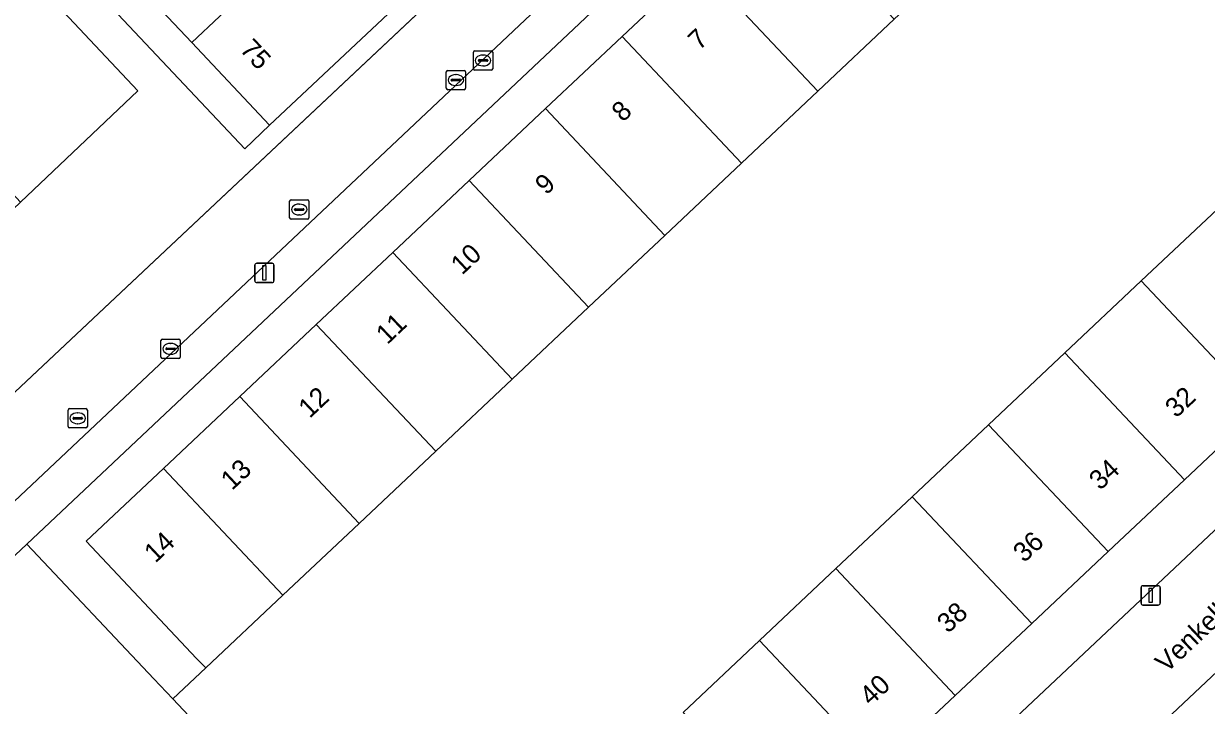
# Model space of a CAD drawing. Extents: x 162542 to 163147, y 380779 to 381521.
# Drawn here: x 162806.1 to 162867.2, y 381217.9 to 381253.1 of the extents above; entities that cross this region are included whole.
import ezdxf

# ---------------------------------------------------------------- set-up
doc = ezdxf.new("R2010")
doc.units = 0
for name, color, linetype in [('IMGEO_Erf', 7, 'Continuous'), ('IMGEO_Groenvoorziening', 7, 'Continuous'), ('IMGEO_Hek', 7, 'Continuous'), ('IMGEO_Kolk', 7, 'Continuous'), ('IMGEO_Lichtmast', 7, 'Continuous'), ('IMGEO_Openbare_ruimte_label', 7, 'Continuous'), ('IMGEO_Pand', 7, 'Continuous'), ('IMGEO_Pand_nummerreeks', 7, 'Continuous'), ('IMGEO_Rioolput', 7, 'Continuous'), ('IMGEO_Voetpad_open', 7, 'Continuous')]:
    doc.layers.add(name, color=color, linetype=linetype)

msp = doc.modelspace()

# ---------------------------------------------------------------- linework, layer by layer
at = {"layer": 'IMGEO_Erf'}
msp.add_lwpolyline([(162792.465, 381275.869), (162788.714, 381279.854), (162784.843, 381283.967), (162781.103, 381287.941), (162777.68, 381291.577), (162773.745, 381295.758), (162770.206, 381299.518), (162766.679, 381303.265), (162762.829, 381307.356), (162758.929, 381311.5), (162757.59, 381310.24), (162817.504, 381246.682), (162818.793, 381247.896), (162814.765, 381252.175), (162810.736, 381256.457), (162807.365, 381260.038), (162803.495, 381264.149), (162799.627, 381268.26), (162795.923, 381272.195)], close=True, dxfattribs=at)
for points in [[(162871.275, 381275.979), (162865.48, 381282.064), (162806.242, 381226.227), (162812.798, 381219.271), (162813.785, 381218.224), (162815.491, 381219.831), (162815.018, 381220.322), (162809.309, 381226.383), (162813.298, 381230.14), (162817.251, 381233.863), (162821.203, 381237.586), (162825.156, 381241.309), (162829.109, 381245.032), (162833.061, 381248.755), (162837.014, 381252.478), (162840.967, 381256.202), (162844.919, 381259.924), (162848.872, 381263.648), (162852.825, 381267.37), (162856.777, 381271.093), (162860.73, 381274.817), (162864.682, 381278.539), (162869.056, 381273.89)], [(162837.429, 381198.492), (162894.031, 381251.782)], [(162870.04, 381233.279), (162866.091, 381229.56), (162862.142, 381225.842), (162858.193, 381222.124), (162854.244, 381218.405), (162850.296, 381214.687)]]:
    msp.add_lwpolyline(points, dxfattribs=at)
at = {"layer": 'IMGEO_Groenvoorziening'}
msp.add_lwpolyline([(162789.418, 381273.655), (162788.933, 381269.872), (162795.678, 381260.305), (162801.834, 381251.14), (162800.589, 381249.668), (162805.915, 381243.918), (162811.977, 381249.676)], close=True, dxfattribs=at)
at = {"layer": 'IMGEO_Hek'}
msp.add_lwpolyline([(162758.166, 381200.425), (162772.303, 381209.99), (162785.212, 381218.724), (162787.433, 381220.358), (162797.686, 381227.138), (162801.587, 381230.307), (162862.582, 381287.674)], dxfattribs=at)
at = {"layer": 'IMGEO_Kolk'}
for p, q in [((162827.922, 381249.806), (162827.922, 381250.658)), ((162827.997, 381250.732), (162828.849, 381250.732)), ((162828.181, 381250.226), (162828.181, 381250.238)), ((162828.224, 381250.275), (162828.622, 381250.275)), ((162828.41, 381250.512), (162828.435, 381250.512)), ((162828.665, 381250.238), (162828.665, 381250.226)), ((162828.923, 381250.658), (162828.923, 381249.806)), ((162828.849, 381249.732), (162827.997, 381249.732)), ((162828.619, 381250.189), (162828.221, 381250.189)), ((162828.433, 381249.952), (162828.408, 381249.952)), ((162813.245, 381236.831), (162814.097, 381236.831)), ((162813.17, 381235.905), (162813.17, 381236.757)), ((162813.429, 381236.325), (162813.429, 381236.337)), ((162813.867, 381236.288), (162813.469, 381236.288)), ((162813.472, 381236.374), (162813.87, 381236.374)), ((162813.658, 381236.611), (162813.683, 381236.611)), ((162813.913, 381236.337), (162813.913, 381236.325)), ((162814.171, 381236.757), (162814.171, 381235.905)), ((162814.097, 381235.831), (162813.245, 381235.831)), ((162813.681, 381236.051), (162813.656, 381236.051))]:
    msp.add_line(p, q, dxfattribs=at)
for points in [[(162827.922, 381249.806), (162827.922, 381250.658)], [(162827.997, 381250.732), (162828.849, 381250.732)], [(162828.923, 381250.658), (162828.923, 381249.806)], [(162828.849, 381249.732), (162827.997, 381249.732)], [(162813.245, 381236.831), (162814.097, 381236.831)], [(162813.17, 381235.905), (162813.17, 381236.757)], [(162814.171, 381236.757), (162814.171, 381235.905)], [(162814.097, 381235.831), (162813.245, 381235.831)]]:
    msp.add_lwpolyline(points, dxfattribs=at)
for centre, radius, start, end in [((162827.999, 381250.656), 0.0765, 91.55205, 178.44795), ((162827.999, 381250.656), 0.0765, 91.55205, 178.44795), ((162828.221, 381250.235), 0.0403, 85.87752, 175.75265), ((162828.626, 381250.237), 0.0386, 1.73085, 96.63898), ((162828.847, 381250.656), 0.0765, 1.55205, 88.44795), ((162828.847, 381250.656), 0.0765, 1.55205, 88.44795), ((162827.999, 381249.808), 0.0765, 181.55205, 268.44795), ((162827.999, 381249.808), 0.0765, 181.55205, 268.44795), ((162828.218, 381250.225), 0.0366, 178.93798, 274.71019), ((162828.622, 381250.232), 0.043, 264.86636, 352.45326), ((162828.847, 381249.808), 0.0765, 271.55205, 358.44795), ((162828.847, 381249.808), 0.0765, 271.55205, 358.44795), ((162813.247, 381236.755), 0.0765, 91.55205, 178.44795), ((162813.247, 381236.755), 0.0765, 91.55205, 178.44795), ((162814.095, 381236.755), 0.0765, 1.55205, 88.44795), ((162814.095, 381236.755), 0.0765, 1.55205, 88.44795), ((162813.469, 381236.334), 0.0403, 85.87752, 175.75265), ((162813.466, 381236.324), 0.0366, 178.93798, 274.71019), ((162813.87, 381236.331), 0.043, 264.86636, 352.45326), ((162813.874, 381236.336), 0.0386, 1.73085, 96.63898), ((162813.247, 381235.907), 0.0765, 181.55205, 268.44795), ((162813.247, 381235.907), 0.0765, 181.55205, 268.44795), ((162814.095, 381235.907), 0.0765, 271.55205, 358.44795), ((162814.095, 381235.907), 0.0765, 271.55205, 358.44795)]:
    msp.add_arc(centre, radius, start, end, dxfattribs=at)
for centre, major_axis, ratio, start_param, end_param in [((162828.409, 381250.232), (-0.387, 0.002), 0.722429, 4.712389, 7.853982), ((162828.434, 381250.232), (-0.39, 0.002), 0.717154, 1.570796, 4.712389), ((162813.657, 381236.331), (-0.387, 0.002), 0.722429, 4.712389, 7.853982), ((162813.682, 381236.331), (-0.39, 0.002), 0.717154, 1.570796, 4.712389)]:
    msp.add_ellipse(centre, major_axis=major_axis, ratio=ratio, start_param=start_param, end_param=end_param, dxfattribs=at)
at = {"layer": 'IMGEO_Lichtmast'}
for p, q in [((162818.026, 381239.858), (162818.026, 381240.658)), ((162818.026, 381240.658), (162818.026, 381239.858)), ((162818.126, 381240.758), (162818.916, 381240.758)), ((162818.916, 381240.758), (162818.126, 381240.758)), ((162819.016, 381240.658), (162819.016, 381239.858)), ((162819.016, 381239.858), (162819.016, 381240.658)), ((162818.916, 381239.758), (162818.126, 381239.758)), ((162818.126, 381239.758), (162818.916, 381239.758)), ((162863.845, 381223.18), (162863.845, 381223.98)), ((162863.845, 381223.98), (162863.845, 381223.18)), ((162863.945, 381224.08), (162864.735, 381224.08)), ((162864.735, 381224.08), (162863.945, 381224.08)), ((162864.835, 381223.98), (162864.835, 381223.18)), ((162864.835, 381223.18), (162864.835, 381223.98)), ((162864.735, 381223.08), (162863.945, 381223.08)), ((162863.945, 381223.08), (162864.735, 381223.08))]:
    msp.add_line(p, q, dxfattribs=at)
for points in [[(162818.446, 381240.633), (162818.596, 381240.633), (162818.596, 381239.883), (162818.446, 381239.883), (162818.446, 381240.633)], [(162864.265, 381223.955), (162864.415, 381223.955), (162864.415, 381223.205), (162864.265, 381223.205), (162864.265, 381223.955)]]:
    msp.add_lwpolyline(points, dxfattribs=at)
for centre, start, end in [((162818.126, 381240.658), 90, 180), ((162818.126, 381240.658), 90, 180), ((162818.916, 381240.658), 0, 90), ((162818.916, 381240.658), 360, 90), ((162818.126, 381239.858), 180, 270), ((162818.126, 381239.858), 180, 270), ((162818.916, 381239.858), 270, 0), ((162818.916, 381239.858), 270, 0), ((162863.945, 381223.98), 90, 180), ((162863.945, 381223.98), 90, 180), ((162864.735, 381223.98), 0, 90), ((162864.735, 381223.98), 360, 90), ((162863.945, 381223.18), 180, 270), ((162863.945, 381223.18), 180, 270), ((162864.735, 381223.18), 270, 0), ((162864.735, 381223.18), 270, 0)]:
    msp.add_arc(centre, 0.1, start, end, dxfattribs=at)
at = {"layer": 'IMGEO_Pand'}
for points in [[(162867.248, 381268.598), (162866.897, 381268.268), (162862.945, 381264.544), (162858.993, 381260.82), (162855.041, 381257.096), (162851.089, 381253.373), (162847.137, 381249.649), (162843.185, 381245.925), (162839.233, 381242.201), (162835.281, 381238.478), (162831.329, 381234.754), (162827.377, 381231.03), (162823.424, 381227.306), (162819.473, 381223.583), (162815.491, 381219.831), (162813.785, 381218.224), (162817.9, 381213.859)], [(162840.173, 381217.524), (162844.121, 381221.244), (162848.069, 381224.963), (162852.016, 381228.683), (162855.964, 381232.402), (162859.912, 381236.122), (162863.86, 381239.842), (162867.807, 381243.561)]]:
    msp.add_lwpolyline(points, dxfattribs=at)
for points in [[(162824.778, 381261.603), (162820.749, 381265.882), (162818.125, 381263.412), (162810.736, 381256.457), (162814.765, 381252.175)], [(162828.807, 381257.324), (162824.778, 381261.603), (162814.765, 381252.175), (162818.793, 381247.896)], [(162851.089, 381253.373), (162844.919, 381259.924), (162840.967, 381256.202), (162847.137, 381249.649)], [(162837.014, 381252.478), (162843.185, 381245.925), (162847.137, 381249.649), (162840.967, 381256.202)], [(162837.014, 381252.478), (162833.061, 381248.755), (162839.233, 381242.201), (162843.185, 381245.925)], [(162839.233, 381242.201), (162833.061, 381248.755), (162829.109, 381245.032), (162835.281, 381238.478)], [(162831.329, 381234.754), (162835.281, 381238.478), (162829.109, 381245.032), (162825.156, 381241.309)], [(162867.807, 381243.561), (162863.86, 381239.842), (162870.04, 381233.279), (162873.988, 381236.997)], [(162831.329, 381234.754), (162825.156, 381241.309), (162821.203, 381237.586), (162827.377, 381231.03)], [(162870.04, 381233.279), (162863.86, 381239.842), (162859.912, 381236.122), (162866.091, 381229.56)], [(162817.251, 381233.863), (162823.424, 381227.306), (162827.377, 381231.03), (162821.203, 381237.586)], [(162862.142, 381225.842), (162866.091, 381229.56), (162859.912, 381236.122), (162855.964, 381232.402)], [(162817.251, 381233.863), (162813.298, 381230.14), (162819.473, 381223.583), (162823.424, 381227.306)], [(162862.142, 381225.842), (162855.964, 381232.402), (162852.016, 381228.683), (162858.193, 381222.124)], [(162815.491, 381219.831), (162819.473, 381223.583), (162813.298, 381230.14), (162809.309, 381226.383), (162815.018, 381220.322)], [(162848.069, 381224.963), (162854.244, 381218.405), (162858.193, 381222.124), (162852.016, 381228.683)], [(162813.785, 381218.224), (162812.798, 381219.271), (162806.242, 381226.227), (162793.366, 381214.11), (162795.692, 381196.614), (162797.681, 381196.886), (162806.61, 381198.095), (162805.675, 381204.999), (162811.719, 381205.817), (162812.612, 381208.879), (162817.9, 381213.859)], [(162848.069, 381224.963), (162844.121, 381221.244), (162850.296, 381214.687), (162854.244, 381218.405)], [(162886.005, 381211.453), (162890.361, 381215.555), (162881.841, 381224.622), (162877.473, 381220.528), (162873.342, 381224.889), (162864.289, 381216.352), (162868.317, 381212.076), (162864.025, 381207.85), (162872.577, 381198.788), (162876.942, 381202.907), (162881.058, 381198.523), (162890.12, 381207.083)], [(162846.347, 381210.968), (162850.296, 381214.687), (162844.121, 381221.244), (162840.173, 381217.524)]]:
    msp.add_lwpolyline(points, close=True, dxfattribs=at)
at = {"layer": 'IMGEO_Rioolput'}
for p, q in [((162829.326, 381250.82), (162829.326, 381251.672)), ((162829.401, 381251.746), (162830.253, 381251.746)), ((162829.814, 381251.526), (162829.839, 381251.526)), ((162830.327, 381251.672), (162830.327, 381250.82)), ((162829.585, 381251.24), (162829.585, 381251.252)), ((162830.023, 381251.203), (162829.625, 381251.203)), ((162829.628, 381251.289), (162830.026, 381251.289)), ((162829.837, 381250.966), (162829.812, 381250.966)), ((162830.069, 381251.252), (162830.069, 381251.24)), ((162830.253, 381250.746), (162829.401, 381250.746)), ((162819.822, 381243.108), (162819.822, 381243.96)), ((162819.897, 381244.034), (162820.749, 381244.034)), ((162820.081, 381243.528), (162820.081, 381243.54)), ((162820.124, 381243.577), (162820.522, 381243.577)), ((162820.31, 381243.814), (162820.335, 381243.814)), ((162820.565, 381243.54), (162820.565, 381243.528)), ((162820.823, 381243.96), (162820.823, 381243.108)), ((162820.749, 381243.034), (162819.897, 381243.034)), ((162820.519, 381243.491), (162820.121, 381243.491)), ((162820.333, 381243.254), (162820.308, 381243.254)), ((162808.368, 381232.314), (162808.368, 381233.166)), ((162808.443, 381233.24), (162809.295, 381233.24)), ((162809.369, 381233.166), (162809.369, 381232.314)), ((162808.627, 381232.734), (162808.627, 381232.746)), ((162809.065, 381232.697), (162808.667, 381232.697)), ((162808.67, 381232.783), (162809.068, 381232.783)), ((162808.856, 381233.02), (162808.881, 381233.02)), ((162809.111, 381232.746), (162809.111, 381232.734)), ((162809.295, 381232.24), (162808.443, 381232.24)), ((162808.879, 381232.46), (162808.854, 381232.46))]:
    msp.add_line(p, q, dxfattribs=at)
for points in [[(162829.326, 381250.82), (162829.326, 381251.672)], [(162829.401, 381251.746), (162830.253, 381251.746)], [(162830.327, 381251.672), (162830.327, 381250.82)], [(162830.253, 381250.746), (162829.401, 381250.746)], [(162819.822, 381243.108), (162819.822, 381243.96)], [(162819.897, 381244.034), (162820.749, 381244.034)], [(162820.823, 381243.96), (162820.823, 381243.108)], [(162820.749, 381243.034), (162819.897, 381243.034)], [(162808.368, 381232.314), (162808.368, 381233.166)], [(162808.443, 381233.24), (162809.295, 381233.24)], [(162809.369, 381233.166), (162809.369, 381232.314)], [(162809.295, 381232.24), (162808.443, 381232.24)]]:
    msp.add_lwpolyline(points, dxfattribs=at)
for centre, radius, start, end in [((162829.403, 381251.67), 0.0765, 91.55205, 178.44795), ((162829.403, 381251.67), 0.0765, 91.55205, 178.44795), ((162830.251, 381251.67), 0.0765, 1.55205, 88.44795), ((162830.251, 381251.67), 0.0765, 1.55205, 88.44795), ((162829.625, 381251.249), 0.0403, 85.87752, 175.75265), ((162829.622, 381251.239), 0.0366, 178.93798, 274.71019), ((162830.026, 381251.246), 0.043, 264.86636, 352.45326), ((162830.03, 381251.251), 0.0386, 1.73085, 96.63898), ((162829.403, 381250.822), 0.0765, 181.55205, 268.44795), ((162829.403, 381250.822), 0.0765, 181.55205, 268.44795), ((162830.251, 381250.822), 0.0765, 271.55205, 358.44795), ((162830.251, 381250.822), 0.0765, 271.55205, 358.44795), ((162819.899, 381243.958), 0.0765, 91.55205, 178.44795), ((162819.899, 381243.958), 0.0765, 91.55205, 178.44795), ((162820.121, 381243.537), 0.0403, 85.87752, 175.75265), ((162820.118, 381243.527), 0.0366, 178.93798, 274.71019), ((162820.522, 381243.534), 0.043, 264.86636, 352.45326), ((162820.526, 381243.539), 0.0386, 1.73085, 96.63898), ((162820.747, 381243.958), 0.0765, 1.55205, 88.44795), ((162820.747, 381243.958), 0.0765, 1.55205, 88.44795), ((162819.899, 381243.11), 0.0765, 181.55205, 268.44795), ((162819.899, 381243.11), 0.0765, 181.55205, 268.44795), ((162820.747, 381243.11), 0.0765, 271.55205, 358.44795), ((162820.747, 381243.11), 0.0765, 271.55205, 358.44795), ((162808.445, 381233.164), 0.0765, 91.55205, 178.44795), ((162808.445, 381233.164), 0.0765, 91.55205, 178.44795), ((162809.293, 381233.164), 0.0765, 1.55205, 88.44795), ((162809.293, 381233.164), 0.0765, 1.55205, 88.44795), ((162808.667, 381232.743), 0.0403, 85.87752, 175.75265), ((162808.664, 381232.733), 0.0366, 178.93798, 274.71019), ((162809.068, 381232.74), 0.043, 264.86636, 352.45326), ((162809.072, 381232.745), 0.0386, 1.73085, 96.63898), ((162808.445, 381232.316), 0.0765, 181.55205, 268.44795), ((162808.445, 381232.316), 0.0765, 181.55205, 268.44795), ((162809.293, 381232.316), 0.0765, 271.55205, 358.44795), ((162809.293, 381232.316), 0.0765, 271.55205, 358.44795)]:
    msp.add_arc(centre, radius, start, end, dxfattribs=at)
for centre, major_axis, ratio, start_param, end_param in [((162829.813, 381251.246), (-0.387, 0.002), 0.722429, 4.712389, 7.853982), ((162829.838, 381251.246), (-0.39, 0.002), 0.717154, 1.570796, 4.712389), ((162820.309, 381243.534), (-0.387, 0.002), 0.722429, 4.712389, 7.853982), ((162820.334, 381243.534), (-0.39, 0.002), 0.717154, 1.570796, 4.712389), ((162808.855, 381232.74), (-0.387, 0.002), 0.722429, 4.712389, 7.853982), ((162808.88, 381232.74), (-0.39, 0.002), 0.717154, 1.570796, 4.712389)]:
    msp.add_ellipse(centre, major_axis=major_axis, ratio=ratio, start_param=start_param, end_param=end_param, dxfattribs=at)
at = {"layer": 'IMGEO_Voetpad_open'}
msp.add_lwpolyline([(162743.002, 381202.706), (162763.302, 381208.084), (162773.466, 381210.777), (162785.212, 381218.724), (162787.433, 381220.358), (162797.686, 381227.138), (162801.587, 381230.307), (162839.922, 381266.362), (162839.214, 381267.113), (162829.602, 381258.072), (162828.807, 381257.324), (162818.793, 381247.896), (162817.504, 381246.682), (162757.59, 381310.24), (162739.401, 381293.119)], dxfattribs=at)
for points in [[(162748.553, 381288.954), (162748.358, 381290.046), (162754.618, 381299.944), (162758.656, 381306.304), (162767.792, 381296.612), (162771.839, 381292.318), (162782.461, 381281.05), (162784.723, 381278.645), (162789.418, 381273.655), (162811.977, 381249.676), (162805.915, 381243.918), (162803.256, 381241.393), (162797.872, 381236.279), (162792.855, 381233.472), (162769.264, 381221.524), (162767.053, 381227.017), (162761.836, 381239.979), (162764.006, 381253.998), (162752.632, 381266.164)], [(162864.115, 381283.64), (162872.439, 381291.347), (162871.434, 381295.246), (162870.795, 381295.515), (162862.582, 381287.674), (162840.913, 381267.294), (162839.922, 381266.362), (162801.587, 381230.307), (162797.686, 381227.138), (162787.433, 381220.358), (162785.212, 381218.724), (162773.466, 381210.777), (162763.302, 381208.084), (162764.861, 381202.201), (162744.562, 381196.817), (162739.9, 381195.582), (162741.119, 381190.891), (162766.134, 381197.592), (162774.367, 381199.798), (162775.779, 381206.104), (162787.491, 381214.105), (162788.325, 381214.675), (162796.372, 381220.172), (162796.565, 381219.956)], [(162793.366, 381214.11), (162806.242, 381226.227), (162865.48, 381282.064), (162864.115, 381283.64), (162796.565, 381219.956), (162789.543, 381213.359), (162787.93, 381211.844), (162790.925, 381193.35), (162794.573, 381190.317), (162797.862, 381166.058), (162798.586, 381160.713), (162800.23, 381148.588), (162800.448, 381146.979), (162802.412, 381147.484), (162795.692, 381196.614)], [(162879.942, 381231.036), (162881.902, 381232.893), (162888.236, 381238.896), (162895.536, 381245.762), (162897.699, 381247.866), (162894.031, 381251.782), (162837.429, 381198.492), (162842.87, 381158.314), (162846.285, 381159.202), (162849.909, 381160.144), (162849.174, 381163.045), (162846.614, 381172.717), (162845.93, 381177.801), (162845.527, 381180.8), (162845.122, 381183.618), (162843.333, 381196.675), (162843.774, 381197.046), (162849.737, 381202.685), (162851.572, 381204.492), (162854.551, 381207.255), (162859.924, 381212.226), (162864.289, 381216.352), (162873.342, 381224.889), (162877.727, 381228.995)]]:
    msp.add_lwpolyline(points, close=True, dxfattribs=at)

# ---------------------------------------------------------------- texts
at = {"layer": 'IMGEO_Openbare_ruimte_label'}
msp.add_text('Venkelhof', height=1, rotation=43.29865, dxfattribs=at).set_placement((162865.164, 381219.532))
at = {"layer": 'IMGEO_Pand_nummerreeks'}
for s, rotation, p in [('7', 43.45461, (162841.006, 381251.734)), ('75', 313.26956, (162817.203, 381251.773)), ('8', 43.59249, (162837.058, 381248.021)), ('9', 43.30905, (162833.096, 381244.252)), ('10', 43.01583, (162828.736, 381240.112)), ('11', 43.59249, (162824.877, 381236.52)), ('12', 43.30905, (162820.861, 381232.702)), ('32', 43.0257, (162865.666, 381232.717)), ('13', 43.00587, (162816.843, 381228.975)), ('34', 42.71978, (162861.729, 381228.976)), ('14', 43.31743, (162812.883, 381225.216)), ('36', 42.49658, (162857.798, 381225.237)), ('38', 42.3244, (162853.863, 381221.581)), ('40', 42.9958, (162849.871, 381217.831))]:
    msp.add_text(s, height=1, rotation=rotation, dxfattribs=at).set_placement(p)

doc.saveas('drawing.dxf')
